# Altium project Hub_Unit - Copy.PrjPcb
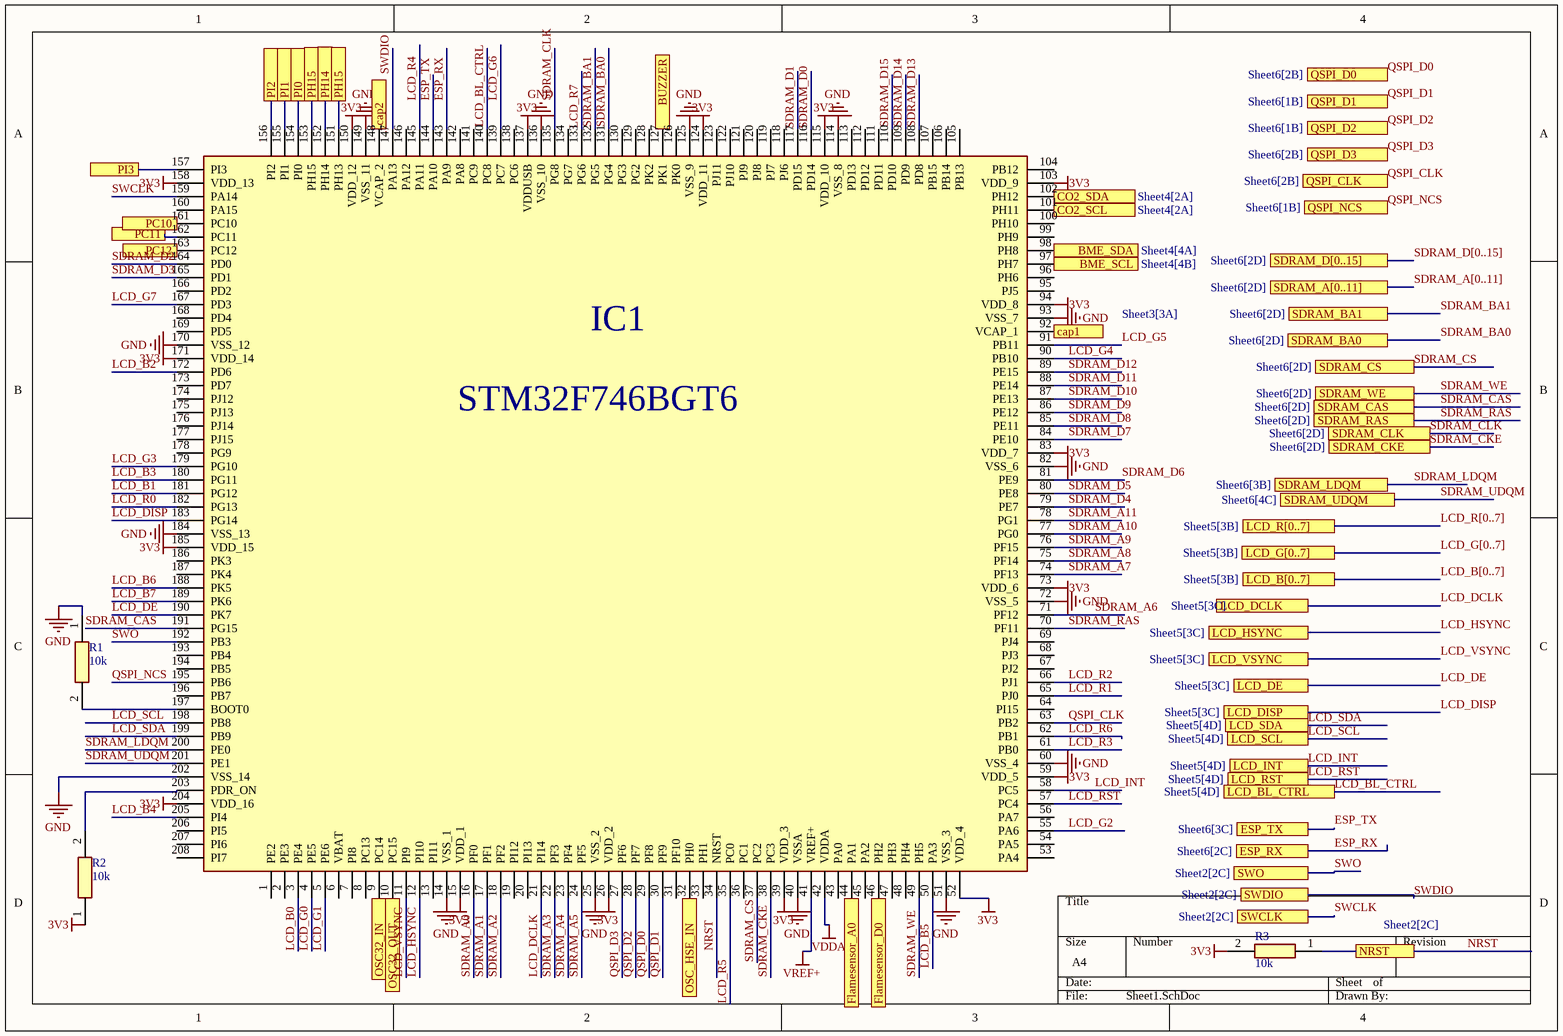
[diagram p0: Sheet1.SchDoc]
6 sheets, 122 parts. Net scope: flat (ports and power ports of the same name join across sheets).
Board file: PCB1.PcbDoc
Sheets:
  Sheet1.SchDoc
  Sheet2.SchDoc
  Sheet3.SchDoc
  Sheet4.SchDoc
  Sheet5.SchDoc
  Sheet6.SchDoc

## Sheet Sheet1.SchDoc
size A4; SheetNumber: 1; SheetTotal: 6

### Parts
IC1  STM32F746BGT6  [QFP50P3000X3000X160-208N]
R1  10k  [RESC1608X55N]
R2  10k  [RESC1608X55N]
R3  10k  [RESC1608X55N]

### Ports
BME_SCL (see Sheet4[4B]), BME_SDA (see Sheet4[4A]), BUZZER, cap1 (see Sheet3[3A]), cap2, CO2_SCL (see Sheet4[2A]), CO2_SDA (see Sheet4[2A]), ESP_RX (see Sheet6[2C]), ESP_TX (see Sheet6[3C]), Flamesensor_A0, Flamesensor_D0, LCD_B[0..7] (see Sheet5[3B]), LCD_BL_CTRL (see Sheet5[4D]), LCD_DCLK (see Sheet5[3C]), LCD_DE (see Sheet5[3C]), LCD_DISP (see Sheet5[3C]), LCD_G[0..7] (see Sheet5[3B]), LCD_HSYNC (see Sheet5[3C]), LCD_INT (see Sheet5[4D]), LCD_R[0..7] (see Sheet5[3B]), LCD_RST (see Sheet5[4D]), LCD_SCL (see Sheet5[4D]), LCD_SDA (see Sheet5[4D]), LCD_VSYNC (see Sheet5[3C]), NRST (see Sheet2[2C]), OSC32_IN, OSC32_OUT, OSC_HSE_IN, PC10, PC11, PC12, PH14, PH15, PI0, PI1, PI2, PI3, QSPI_CLK (see Sheet6[2B]), QSPI_D0 (see Sheet6[2B]), QSPI_D1 (see Sheet6[1B]), QSPI_D2 (see Sheet6[1B]), QSPI_D3 (see Sheet6[2B]), QSPI_NCS (see Sheet6[1B]), SDRAM_A[0..11] (see Sheet6[2D]), SDRAM_BA0 (see Sheet6[2D]), SDRAM_BA1 (see Sheet6[2D]), SDRAM_CAS (see Sheet6[2D]), SDRAM_CKE (see Sheet6[2D]), SDRAM_CLK (see Sheet6[2D]), SDRAM_CS (see Sheet6[2D]), SDRAM_D[0..15] (see Sheet6[2D]), SDRAM_LDQM (see Sheet6[3B]), SDRAM_RAS (see Sheet6[2D]), SDRAM_UDQM (see Sheet6[4C]), SDRAM_WE (see Sheet6[2D]), SWCLK (see Sheet2[2C]), SWDIO (see Sheet2[2C]), SWO (see Sheet2[2C])

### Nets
3V3: IC1.15(VDD_1) IC1.26(VDD_2) IC1.39(VDD_3) IC1.52(VDD_4) IC1.59(VDD_5) IC1.73(VDD_6) IC1.83(VDD_7) IC1.94(VDD_8) IC1.103(VDD_9) IC1.115(VDD_10) IC1.124(VDD_11) IC1.137(VDDUSB) IC1.150(VDD_12) IC1.158(VDD_13) IC1.171(VDD_14) IC1.185(VDD_15) IC1.204(VDD_16) R2.1 R3.2
GND: IC1.14(VSS_1) IC1.25(VSS_2) IC1.40(VSSA) IC1.51(VSS_3) IC1.60(VSS_4) IC1.72(VSS_5) IC1.82(VSS_6) IC1.93(VSS_7) IC1.114(VSS_8) IC1.125(VSS_9) IC1.136(VSS_10) IC1.149(VSS_11) IC1.170(VSS_12) IC1.184(VSS_13) IC1.202(VSS_14) R1.1
VDDA: IC1.42(VDDA)
VREF+: IC1.41(VREF+)
ESP_RX: IC1.143(PA9) ; port ESP_RX
ESP_TX: IC1.144(PA10) ; port ESP_TX
LCD_B0: IC1.3(PE4)
LCD_B1: IC1.181(PG12)
LCD_B2: IC1.172(PD6)
LCD_B3: IC1.180(PG11)
LCD_B4: IC1.205(PI4)
LCD_B5: IC1.50(PA3)
LCD_B6: IC1.188(PK5)
LCD_B7: IC1.189(PK6)
LCD_BL_CTRL: IC1.140(PC8) ; port LCD_BL_CTRL
LCD_DCLK: IC1.21(PI14) ; port LCD_DCLK
LCD_DE: IC1.190(PK7) ; port LCD_DE
LCD_DISP: IC1.183(PG14) ; port LCD_DISP
LCD_G0: IC1.4(PE5)
LCD_G1: IC1.5(PE6)
LCD_G2: IC1.55(PA6)
LCD_G3: IC1.179(PG10)
LCD_G4: IC1.90(PB10)
LCD_G5: IC1.91(PB11)
LCD_G6: IC1.139(PC7)
LCD_G7: IC1.167(PD3)
LCD_HSYNC: IC1.12(PI10) ; port LCD_HSYNC
LCD_INT: IC1.58(PC5) ; port LCD_INT
LCD_R0: IC1.182(PG13)
LCD_R1: IC1.65(PJ0)
LCD_R2: IC1.66(PJ1)
LCD_R3: IC1.61(PB0)
LCD_R4: IC1.145(PA11)
LCD_R5: IC1.35(PC0)
LCD_R6: IC1.62(PB1)
LCD_R7: IC1.133(PG6)
LCD_RST: IC1.57(PC4) ; port LCD_RST
LCD_SCL: IC1.198(PB8) ; port LCD_SCL
LCD_SDA: IC1.199(PB9) ; port LCD_SDA
LCD_VSYNC: IC1.11(PI9) ; port LCD_VSYNC
NRST: IC1.34(NRST) R3.1 ; port NRST
QSPI_CLK: IC1.63(PB2) ; port QSPI_CLK
QSPI_D0: IC1.29(PF8) ; port QSPI_D0
QSPI_D1: IC1.30(PF9) ; port QSPI_D1
QSPI_D2: IC1.28(PF7) ; port QSPI_D2
QSPI_D3: IC1.27(PF6) ; port QSPI_D3
QSPI_NCS: IC1.195(PB6) ; port QSPI_NCS
SDRAM_A0: IC1.16(PF0)
SDRAM_A1: IC1.17(PF1)
SDRAM_A2: IC1.18(PF2)
SDRAM_A3: IC1.22(PF3)
SDRAM_A4: IC1.23(PF4)
SDRAM_A5: IC1.24(PF5)
SDRAM_A6: IC1.71(PF12)
SDRAM_A7: IC1.74(PF13)
SDRAM_A8: IC1.75(PF14)
SDRAM_A9: IC1.76(PF15)
SDRAM_A10: IC1.77(PG0)
SDRAM_A11: IC1.78(PG1)
SDRAM_BA0: IC1.131(PG4) ; port SDRAM_BA0
SDRAM_BA1: IC1.132(PG5) ; port SDRAM_BA1
SDRAM_CAS: IC1.191(PG15) ; port SDRAM_CAS
SDRAM_CKE: IC1.38(PC3) ; port SDRAM_CKE
SDRAM_CLK: IC1.135(PG8) ; port SDRAM_CLK
SDRAM_CS: IC1.37(PC2) ; port SDRAM_CS
SDRAM_D0: IC1.116(PD14)
SDRAM_D1: IC1.117(PD15)
SDRAM_D2: IC1.164(PD0)
SDRAM_D3: IC1.165(PD1)
SDRAM_D4: IC1.79(PE7)
SDRAM_D5: IC1.80(PE8)
SDRAM_D6: IC1.81(PE9)
SDRAM_D7: IC1.84(PE10)
SDRAM_D8: IC1.85(PE11)
SDRAM_D9: IC1.86(PE12)
SDRAM_D10: IC1.87(PE13)
SDRAM_D11: IC1.88(PE14)
SDRAM_D12: IC1.89(PE15)
SDRAM_D13: IC1.108(PD8)
SDRAM_D14: IC1.109(PD9)
SDRAM_D15: IC1.110(PD10)
SDRAM_LDQM: IC1.200(PE0) ; port SDRAM_LDQM
SDRAM_RAS: IC1.70(PF11) ; port SDRAM_RAS
SDRAM_UDQM: IC1.201(PE1) ; port SDRAM_UDQM
SDRAM_WE: IC1.49(PH5) ; port SDRAM_WE
SWCLK: IC1.159(PA14) ; port SWCLK
SWDIO: IC1.147(PA13) ; port SWDIO
SWO: IC1.192(PB3) ; port SWO
NetC6_1: IC1.148(VCAP_2) ; port cap2
NetC7_1: IC1.92(VCAP_1) ; port cap1
NetC22_2: IC1.9(PC14) ; port OSC32_IN
NetC23_2: IC1.10(PC15) ; port OSC32_OUT
NetC41_2: IC1.44(PA1) ; port Flamesensor_A0
NetIC1_32: IC1.32(PH0) ; port OSC_HSE_IN
NetIC1_46: IC1.46(PH2) ; port Flamesensor_D0
NetIC1_97: IC1.97(PH7) ; port BME_SCL
NetIC1_98: IC1.98(PH8) ; port BME_SDA
NetIC1_101: IC1.101(PH11) ; port CO2_SCL
NetIC1_102: IC1.102(PH12) ; port CO2_SDA
NetIC1_127: IC1.127(PK1) ; port BUZZER
NetIC1_151: IC1.151(PH13) IC1.153(PH15) ; port PH15
NetIC1_152: IC1.152(PH14) ; port PH14
NetIC1_154: IC1.154(PI0) ; port PI0
NetIC1_155: IC1.155(PI1) ; port PI1
NetIC1_156: IC1.156(PI2) ; port PI2
NetIC1_157: IC1.157(PI3) ; port PI3
NetIC1_161: IC1.161(PC10) ; port PC10
NetIC1_162: IC1.162(PC11) ; port PC11
NetIC1_163: IC1.163(PC12) ; port PC12
NetIC1_197: IC1.197(BOOT0) R1.2
NetIC1_203: IC1.203(PDR_ON) R2.2

Not connected (* = marked no-connect by the designer): IC1 1(PE2) 2(PE3) 6(VBAT) 7(PI8) 8(PC13) 13(PI11) 19(PI12) 20(PI13) 31(PF10) 33(PH1) 36(PC1) 43(PA0) 45(PA2) 47(PH3) 48(PH4) 53(PA4) 54(PA5) 56(PA7) 64(PI15) 67(PJ2) 68(PJ3) 69(PJ4) 95(PJ5) 96(PH6) 99(PH9) 100(PH10) 104(PB12) 105(PB13) 106(PB14) 107(PB15) 111(PD11) 112(PD12) 113(PD13) 118(PJ6) 119(PJ7) 120(PJ8) 121(PJ9) 122(PJ10) 123(PJ11) 126(PK0) 128(PK2) 129(PG2) 130(PG3) 134(PG7) 138(PC6) 141(PC9) 142(PA8) 146(PA12) 160(PA15) 166(PD2) 168(PD4) 169(PD5) 173(PD7) 174(PJ12) 175(PJ13) 176(PJ14) 177(PJ15) 178(PG9) 186(PK3) 187(PK4) 193(PB4) 194(PB5) 196(PB7) 206(PI5) 207(PI6) 208(PI7)

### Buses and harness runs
bus LCD_B[0..7] = port LCD_B[0..7]
bus LCD_G[0..7] = port LCD_G[0..7]
bus LCD_R[0..7] = port LCD_R[0..7]
bus SDRAM_A[0..11] = port SDRAM_A[0..11]
bus SDRAM_D[0..15] = port SDRAM_D[0..15]

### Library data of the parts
IC1 = STM32F746BGT6: Integrated Circuit; Manufacturer_Name: STMicroelectronics
R1-R3 = RC0603FR-071KL: Resistor; Manufacturer_Name: YAGEO

## Sheet Sheet2.SchDoc
size A4; SheetNumber: 2; SheetTotal: 6
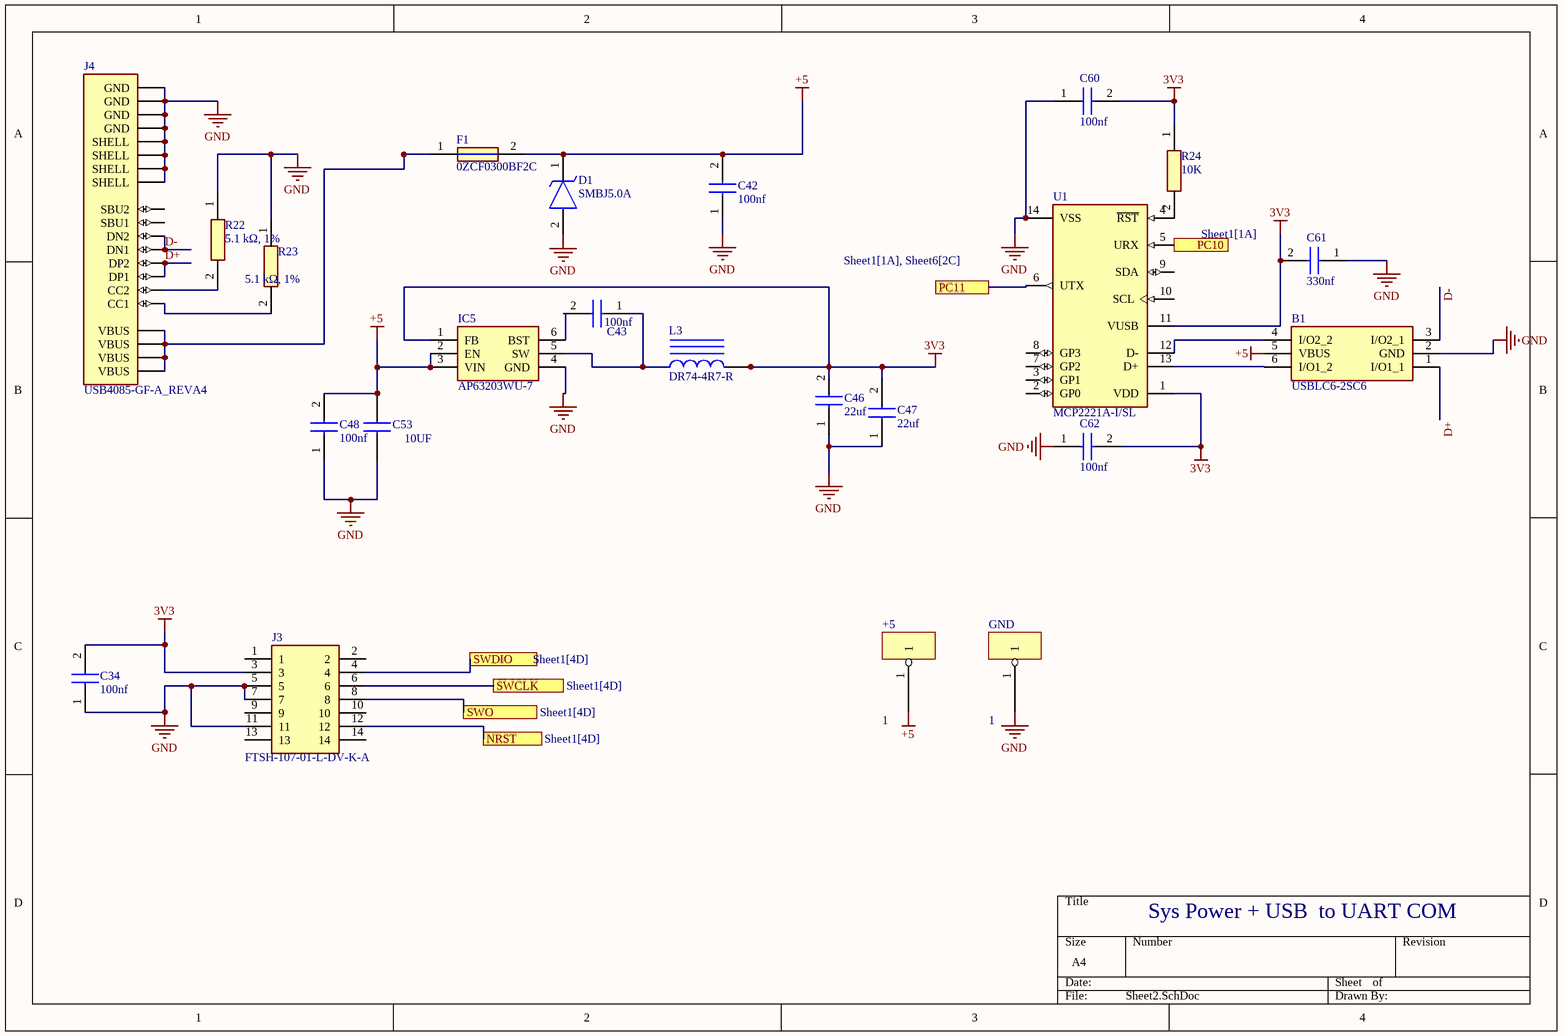
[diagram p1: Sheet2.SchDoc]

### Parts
+5  1  [ANT]
B1  USBLC6-2SC6  [SOT95P280X145-6N]
C34  100nf  [CAPC1608X95N]
C42  100nf  [CAPC1608X95N]
C43  100nf  [CAPC1608X95N]
C46  22uf  [CAPC1608X95N]
C47  22uf  [CAPC1608X95N]
C48  100nf  [CAPC1608X95N]
C53  10UF  [CAPC1608X90N]
C60  100nf  [CAPC1608X95N]
C61  330nf  [CAPC1608X95N]
C62  100nf  [CAPC1608X95N]
D1  SMBJ5.0A  [SMBJ12A]
F1  0ZCF0300BF2C  [FUSC7451X115N]
GND  1  [ANT]
IC5  AP63203WU-7  [AP63203WU7]
J3  FTSH-107-01-L-DV-K-A  [FTSH-107-XX-YYY-DV-K-A]
J4  USB4085-GF-A_REVA4  [GCT_USB4085-GF-A_REVA4]
L3  DR74-4R7-R  [COBU-DR74-4R7-R_V]
R22  5.1 kΩ, 1%  [RESC1608X55N]
R23  5.1 kΩ, 1%  [RESC1608X55N]
R24  10K  [RESC1608X55N]
U1  MCP2221A-I/SL  [FP-C04-065-SL-MFG]

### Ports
NRST (see Sheet1[4D]), PC10 (see Sheet1[1A]), PC11 (see Sheet1[1A], Sheet6[2C]), SWCLK (see Sheet1[4D]), SWDIO (see Sheet1[4D]), SWO (see Sheet1[4D])

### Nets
3V3: C34.2 C46.2 C47.2 C60.2 C61.2 C62.2 IC5.1(FB) J3.3 L3.2 R24.1 U1.1(VDD) U1.11(VUSB)
+5: +5.1 B1.5(VBUS) C42.2 C48.2 C53.2 D1.1(K) F1.2 IC5.2(EN) IC5.3(VIN)
GND: B1.2(GND) C34.1 C42.1 C46.1 C47.1 C48.1 C53.1 C60.1 C61.1 C62.1 D1.2(A) GND.1 IC5.4(GND) J3.5 J3.7 J3.11 J4.A1(GND) J4.A12(GND) J4.B1(GND) J4.B12(GND) J4.S1(SHELL) J4.S2(SHELL) J4.S3(SHELL) J4.S4(SHELL) R22.1 R23.1 U1.14(VSS)
D+: B1.1(I/O1_1) J4.A6(DP1) J4.B6(DP2)
D-: B1.3(I/O2_1) J4.A7(DN1) J4.B7(DN2)
NRST: J3.12 ; port NRST
SWCLK: J3.6 ; port SWCLK
SWDIO: J3.4 ; port SWDIO
SWO: J3.8 ; port SWO
NetB1_4: B1.4(I/O2_2) U1.12(D-)
NetB1_6: B1.6(I/O1_2) U1.13(D+)
NetC43_1: C43.1 IC5.5(SW) L3.1
NetC43_2: C43.2 IC5.6(BST)
NetF1_1: F1.1 J4.A4(VBUS) J4.A9(VBUS) J4.B4(VBUS) J4.B9(VBUS)
NetIC1_161: U1.5(URX) ; port PC10
NetIC1_162: U1.6(UTX) ; port PC11
NetJ4_A5: J4.A5(CC1) R23.2
NetJ4_B5: J4.B5(CC2) R22.2
NetR24_2: R24.2 U1.4(~{RST})

Not connected (* = marked no-connect by the designer): J3 1 2 9 10 13 14; J4 A8(SBU1) B8(SBU2); U1 2(GP0) 3(GP1) 7(GP2) 8(GP3) 9(SDA) 10(SCL)

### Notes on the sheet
- Sys Power + USB  to UART COM

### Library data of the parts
B1 = USBLC6-2SC6: TVS Diode Array Uni-Directional USBLC6-2SC6 17V, SOT-23 6-Pin; Manufacturer_Name: STMicroelectronics; Geometry.Height: 1.45mm
C34 C42 C43 C46-C48 C60-C62 = VJ0603Y104KXACW1BC: Capacitor; Manufacturer_Name: Vishay
C53 = CL10A106KP8NNNC: 10F +/-10% 10V Ceramic Capacitor X5R 0603 (1608 Metric); Manufacturer_Name: SAMSUNG; Geometry.Height: 0.9mm
D1 = SMBJ5.0A: TVS Diode (Uni-directional); Manufacturer_Name: STMicroelectronics
F1 = 0ZCF0300BF2C: Fuse; Manufacturer_Name: BelFuse
IC5 = AP63203WU-7: Integrated Circuit; Manufacturer_Name: Diodes Incorporated
J3 = FTSH-107-01-L-DV-K-A: Connector; Manufacturer_Name: SAMTEC
J4 = USB4085-GF-A_REVA4: USB-C (USB TYPE-C) USB 2.0 Receptacle Connector 24 (16+8 Dummy) Position Through Hole, Right Angle, low cost, 3.46mm profile, 16 pin, horizontal, Top mount; MF: Global Connector Technology
L3 = CMP-2000-06180-1: High Power Density, High Efficiency, Shielded Inductor, 4.7 uH, -40 to 125 degC, RoHS, Tape and Reel; Manufacturer: Eaton; Tolerance: ±20%; Current - Saturation: 4.37A; Type: Wirewound; Frequency - Test: 100kHz; Current Rating: 3.34A; DC Resistance (DCR): 25.4mOhm; Inductance: 4.7µH; Material - Core: Ferrite
R22-R24 = RC0603FR-071KL: Resistor; Manufacturer_Name: YAGEO
U1 = CMP-06284-000011-1: IC USB TO I2C/UART 14SOIC; Manufacturer: Microchip; Min Supply Voltage: 3V; Usb Standard: USB 2.0; Max Supply Voltage: 5.5V; Nominal Supply Current: 10-13mA; Automotive Grade: Grade 3; Interface: I2C,UART,USB; Standoff Height: 0.1mm; Max Junction Temp: +150°C; Data Rate: 12Mbits/s

## Sheet Sheet3.SchDoc
size A4; SheetNumber: 3; SheetTotal: 6
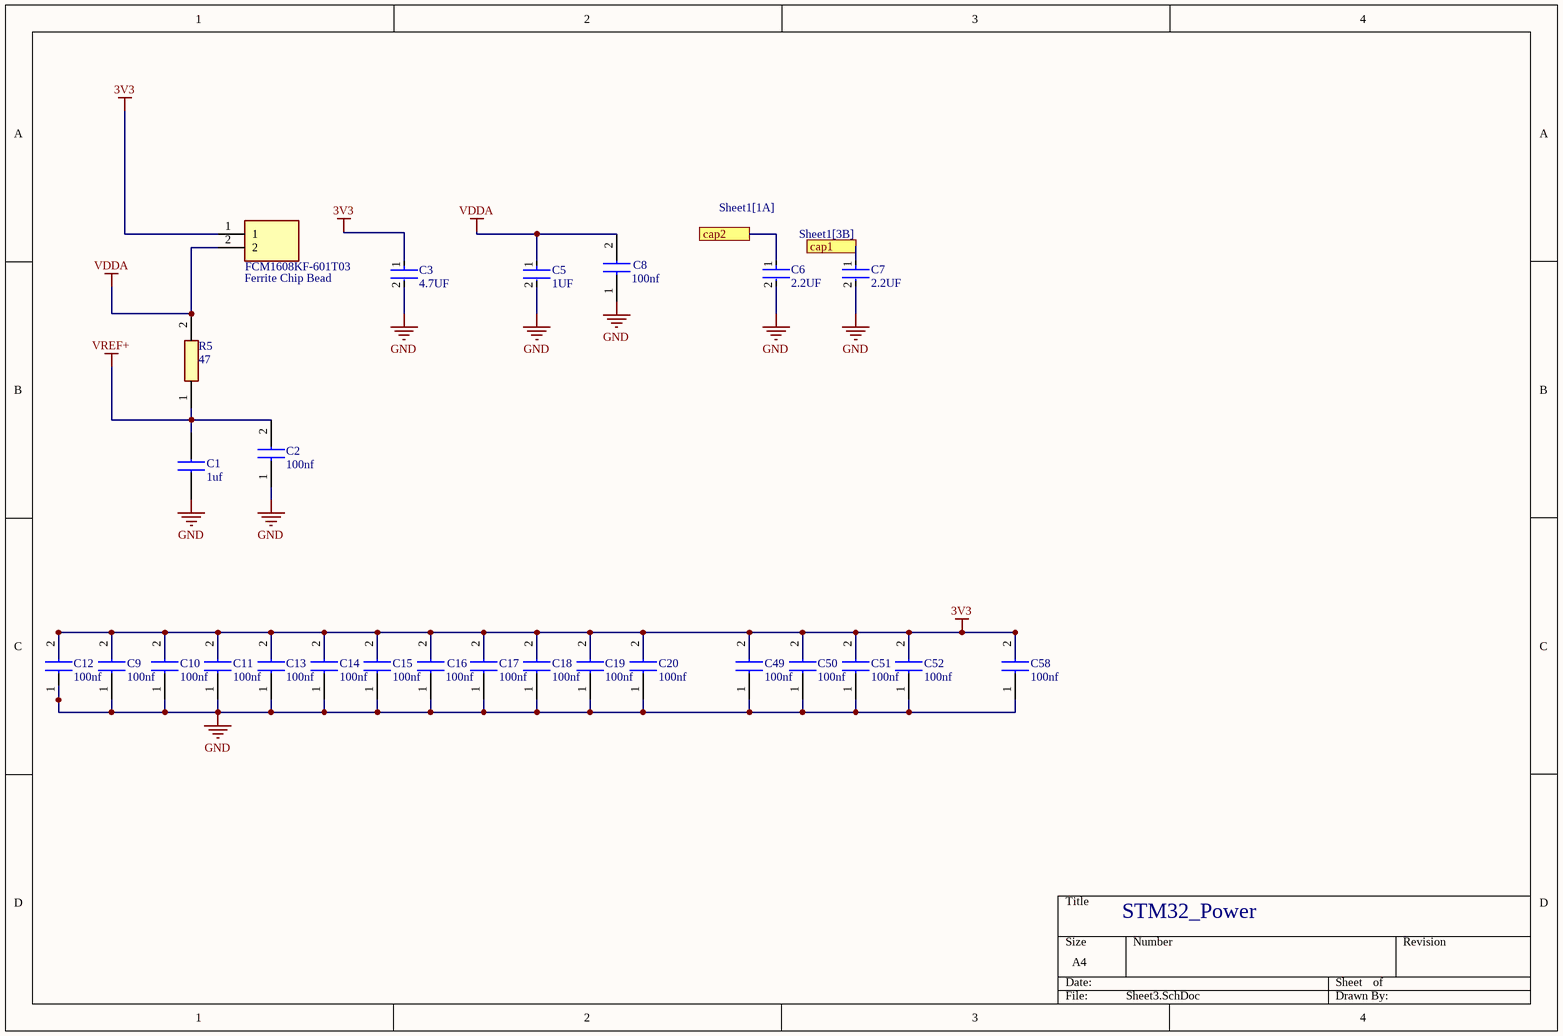
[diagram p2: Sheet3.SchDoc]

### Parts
C1  1uf  [CAPC1608X95N]
C2  100nf  [CAPC1608X95N]
C3  4.7UF  [FP-CL10-IPC_A]
C5  1UF  [FP-CL10-IPC_A]
C6  2.2UF  [FP-CL10-IPC_A]
C7  2.2UF  [FP-CL10-IPC_A]
C8  100nf  [CAPC1608X95N]
C9  100nf  [CAPC1608X95N]
C10  100nf  [CAPC1608X95N]
C11  100nf  [CAPC1608X95N]
C12  100nf  [CAPC1608X95N]
C13  100nf  [CAPC1608X95N]
C14  100nf  [CAPC1608X95N]
C15  100nf  [CAPC1608X95N]
C16  100nf  [CAPC1608X95N]
C17  100nf  [CAPC1608X95N]
C18  100nf  [CAPC1608X95N]
C19  100nf  [CAPC1608X95N]
C20  100nf  [CAPC1608X95N]
C49  100nf  [CAPC1608X95N]
C50  100nf  [CAPC1608X95N]
C51  100nf  [CAPC1608X95N]
C52  100nf  [CAPC1608X95N]
C58  100nf  [CAPC1608X95N]
Ferrite_Chip_Bead  FCM1608KF-601T03  [BEADC1608X95N]
R5  47  [RESC1608X55N]

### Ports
cap1 (see Sheet1[3B]), cap2 (see Sheet1[1A])

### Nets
3V3: C3.1 C9.2 C10.2 C11.2 C12.2 C13.2 C14.2 C15.2 C16.2 C17.2 C18.2 C19.2 C20.2 C49.2 C50.2 C51.2 C52.2 C58.2 Ferrite_Chip_Bead.1
GND: C1.1 C2.1 C3.2 C5.2 C6.2 C7.2 C8.1 C9.1 C10.1 C11.1 C12.1 C13.1 C14.1 C15.1 C16.1 C17.1 C18.1 C19.1 C20.1 C49.1 C50.1 C51.1 C52.1 C58.1
VDDA: C5.1 C8.2 Ferrite_Chip_Bead.2 R5.2
VREF+: C1.2 C2.2 R5.1
NetC6_1: C6.1 ; port cap2
NetC7_1: C7.1 ; port cap1

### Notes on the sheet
- STM32_Power

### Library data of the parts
C1 = 0603X105K250CT: WALSIN - 0603X105K250CT - SMD Multilayer Ceramic Capacitor, 1 F, 25 V, 0603 [1608 Metric], +/- 10%, X5R; Manufacturer_Name: Walsin Technology Corporation; Geometry.Height: 0.95mm
C2 C8-C20 C49-C52 C58 = VJ0603Y104KXACW1BC: Capacitor; Manufacturer_Name: Vishay
C3 C5-C7 = CMP-13271-003582-1: Cap Ceramic 2.2uF 10V X7R ±10% Pad SMD 0603 +125°C T/R
Ferrite_Chip_Bead = FCM1608KF-601T03: Ferrite Bead; Manufacturer_Name: TAI-TECH
R5 = RC0603FR-071KL: Resistor; Manufacturer_Name: YAGEO

## Sheet Sheet4.SchDoc
size A4; SheetNumber: 4; SheetTotal: 6
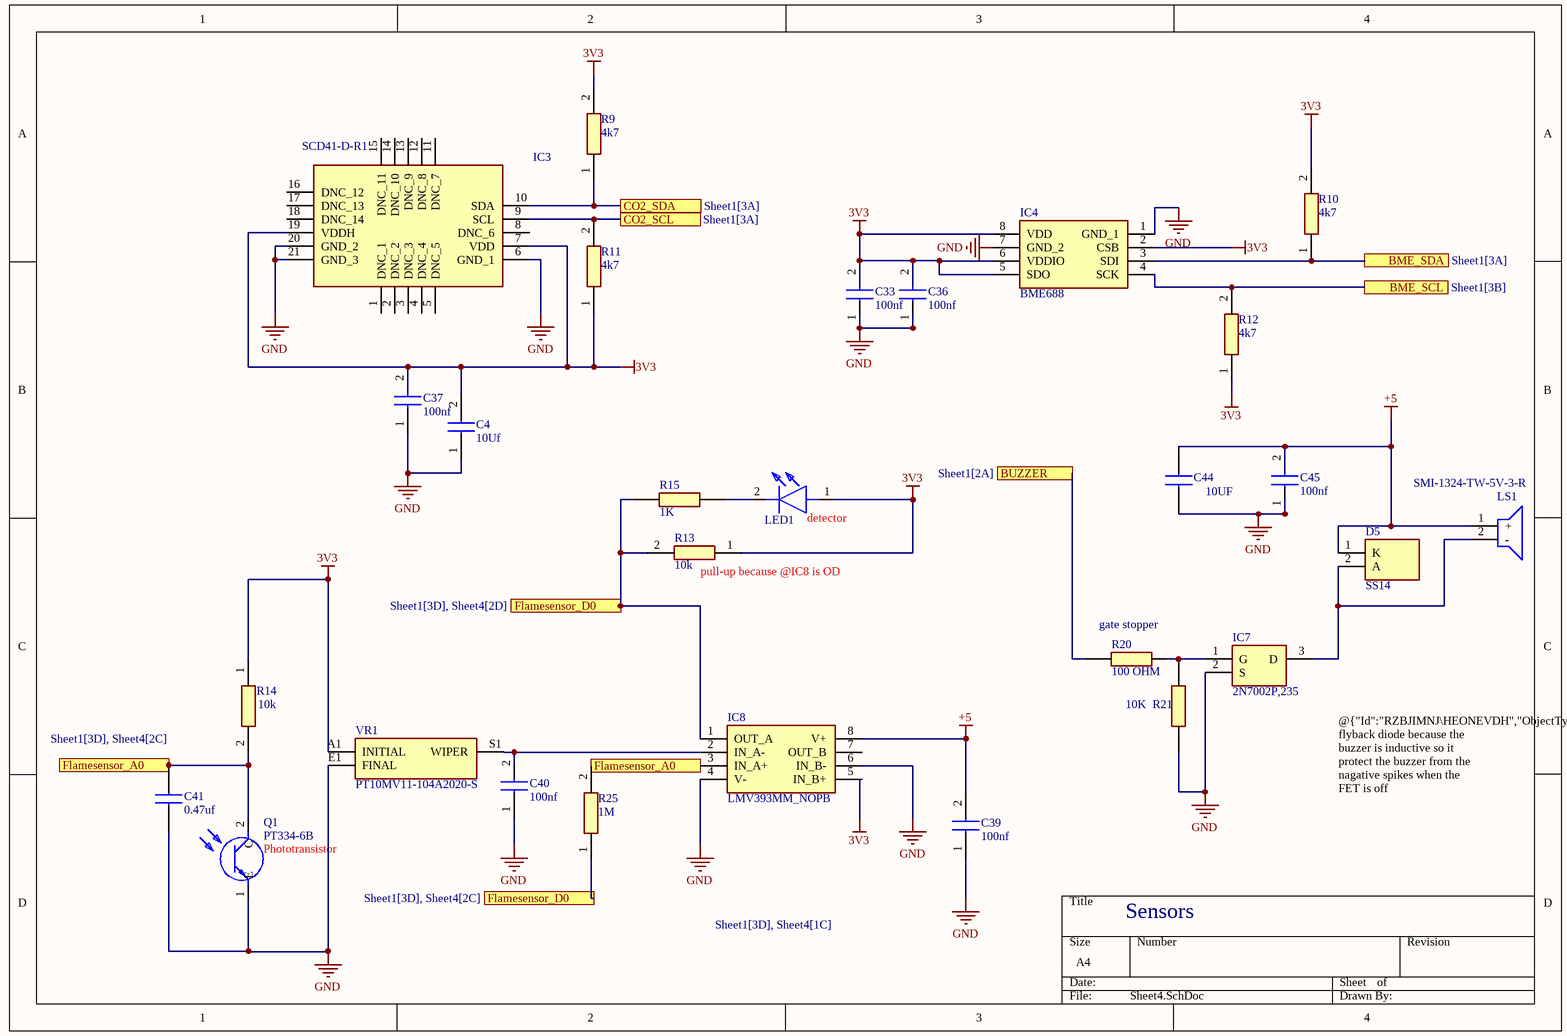
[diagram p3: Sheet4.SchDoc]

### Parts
C4  10Uf  [CAPC1608X95N]
C33  100nf  [CAPC1608X95N]
C36  100nf  [CAPC1608X95N]
C37  100nf  [CAPC1608X95N]
C39  100nf  [CAPC1608X95N]
C40  100nf  [CAPC1608X95N]
C41  0.47uf  [CAPC1608X90N]
C44  10UF  [CAPC1608X90N]
C45  100nf  [CAPC1608X95N]
D5  SS14  [DIOM5026X262N]
IC3  SCD41-D-R1  [SCD41DR1]
IC4  BME688  [BME688]
IC7  2N7002P,235  [SOT95P230X110-3N]
IC8  LMV393MM_NOPB  [SOP65P490X110-8N]
LED1  KPTL-3216SURCK-01-VS  [KPTL3216SURCK01VS]  (value not drawn)
LS1  SMI-1324-TW-5V-3-R  [SMI1324TW5V3R]
Q1  PT334-6B  [PT3346B]
R9  4k7  [RESC1608X55N]
R10  4k7  [RESC1608X55N]
R11  4k7  [RESC1608X55N]
R12  4k7  [RESC1608X55N]
R13  10k  [RESC1608X55N]
R14  10k  [RESC1608X55N]
R15  1K  [RESC1608X50N]
R20  100 OHM  [RESC1608X55N]
R21  10K  [RESC1608X50N]
R25  1M  [RESC1608X55N]
VR1  PT10MV11-104A2020-S  [PT10MV11104A2020S]

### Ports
BME_SCL (see Sheet1[3B]), BME_SDA (see Sheet1[3A]), BUZZER (see Sheet1[2A]), CO2_SCL (see Sheet1[3A]), CO2_SDA (see Sheet1[3A]), Flamesensor_A0 (see Sheet1[3D], Sheet4[1C]), Flamesensor_A0 (see Sheet1[3D], Sheet4[2C]), Flamesensor_D0 (see Sheet1[3D], Sheet4[2C]), Flamesensor_D0 (see Sheet1[3D], Sheet4[2D])

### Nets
3V3: C4.2 C33.2 C36.2 C37.2 IC3.7(VDD) IC3.19(VDDH) IC4.2(CSB) IC4.5(SDO) IC4.6(VDDIO) IC4.8(VDD) IC8.5(IN_B+) LED1.1(A) R9.2 R10.2 R11.1 R12.1 R13.1 R14.1 VR1.A1(INITIAL)
+5: C39.2 C44.2 C45.2 D5.1(K) IC8.8(V+) LS1.1(+)
GND: C4.1 C33.1 C36.1 C37.1 C39.1 C40.1 C41.1 C44.1 C45.1 IC3.6(GND_1) IC3.20(GND_2) IC3.21(GND_3) IC4.1(GND_1) IC4.7(GND_2) IC7.2(S) IC8.4(V-) IC8.6(IN_B-) Q1.1(E) R21.1 VR1.E1(FINAL)
NetC40_2: C40.2 IC8.2(IN_A-) VR1.S1(WIPER)
NetC41_2: C41.2 IC8.3(IN_A+) Q1.2(C) R14.2 R25.2 ; port Flamesensor_A0
NetD5_2: D5.2(A) IC7.3(D) LS1.2(-)
NetIC1_46: IC8.1(OUT_A) R13.2 R15.1 R25.1 ; port Flamesensor_D0
NetIC1_97: IC4.4(SCK) R12.2 ; port BME_SCL
NetIC1_98: IC4.3(SDI) R10.1 ; port BME_SDA
NetIC1_101: IC3.9(SCL) R11.2 ; port CO2_SCL
NetIC1_102: IC3.10(SDA) R9.1 ; port CO2_SDA
NetIC1_127: R20.1 ; port BUZZER
NetIC7_1: IC7.1(G) R20.2 R21.2
NetLED1_2: LED1.2(K) R15.2

Not connected (* = marked no-connect by the designer): IC3 1(DNC_1) 2(DNC_2) 3(DNC_3) 4(DNC_4) 5(DNC_5) 8(DNC_6) 11(DNC_7) 12(DNC_8) 13(DNC_9) 14(DNC_10) 15(DNC_11) 16(DNC_12) 17(DNC_13) 18(DNC_14); IC8 7(OUT_B)

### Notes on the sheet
- (near R13) pull-up because @IC8 is OD
- (near LED1) detector
- (near R20) gate stopper
- @{"Id":"RZBJIMNJ\HEONEVDH","ObjectType":2}
  flyback diode because the buzzer is inductive so it protect the buzzer from the nagative spikes when the FET is off
- (near Q1) Phototransistor
- Sensors

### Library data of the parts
C4 C33 C36 C37 C39 C40 C45 = VJ0603Y104KXACW1BC: Capacitor; Manufacturer_Name: Vishay
C41 = CC0603KRX7R6BB474: Phycomp 0603 Standard 470nF Ceramic Multilayer Capacitor, 10 V dc, +125C, X7R Dielectric, +/-10% SMD; Manufacturer_Name: KEMET; Geometry.Height: 0.9mm
C44 = CL10A106KP8NNNC: as C53 on sheet Sheet2
D5 = SS14: Battery; Manufacturer_Name: HY Electronic
IC3 = SCD41-D-R1: Integrated Circuit; Manufacturer_Name: Sensirion
IC4 = BME688: Integrated Circuit; Manufacturer_Name: BOSCH
IC7 = 2N7002P,235: Integrated Circuit; Manufacturer_Name: Nylofix
IC8 = LMV393MM_NOPB: Integrated Circuit; Manufacturer_Name: Texas Instruments; Manufacturer_Part_Number: LMV393MM/NOPB
LED1 = KPTL-3216SURCK-01-VS: LED; Manufacturer_Name: Kingbright
LS1 = SMI-1324-TW-5V-3-R: Loudspeaker or Buzzer; Manufacturer_Name: PUI Audio
Q1 = PT334-6B: Phototransistor; Manufacturer_Name: Everlight
R9-R12 = CRCW06034K70JNEAC: Resistor; Manufacturer_Name: Vishay
R13 R14 R25 = RC0603FR-071KL: Resistor; Manufacturer_Name: YAGEO
R15 = CRCW06031K00FKEA: CRCW0603 Resistor T/R 0.10W,1%,1K Vishay CRCW Series Thick Film Surface Mount Resistor 0603 Case 1k +/-1% 0.1W +/-100ppm/C; Geometry.Height: 0.5mm
R20 = TNPW0603100RFHEA: Res Thin Film 0603 100 Ohm 1% 0.1W(1/10W) +/-50ppm/C Sulfur Resistant Pad SMD Automotive Medical T/R; Manufacturer_Name: Vishay; Geometry.Height: 0.55mm
R21 = RCA0603100KFKEA: 100 kOhms +/-1% 0.1W, 1/10W Chip Resistor 0603 (1608 Metric) Anti-Sulfur, Automotive AEC-Q200 Thick Film; Manufacturer_Name: Vishay; Geometry.Height: 0.5mm
VR1 = PT10MV11-104A2020-S: Variable Resistor; Manufacturer_Name: PIHER

## Sheet Sheet5.SchDoc
size A4; SheetNumber: 5; SheetTotal: 6
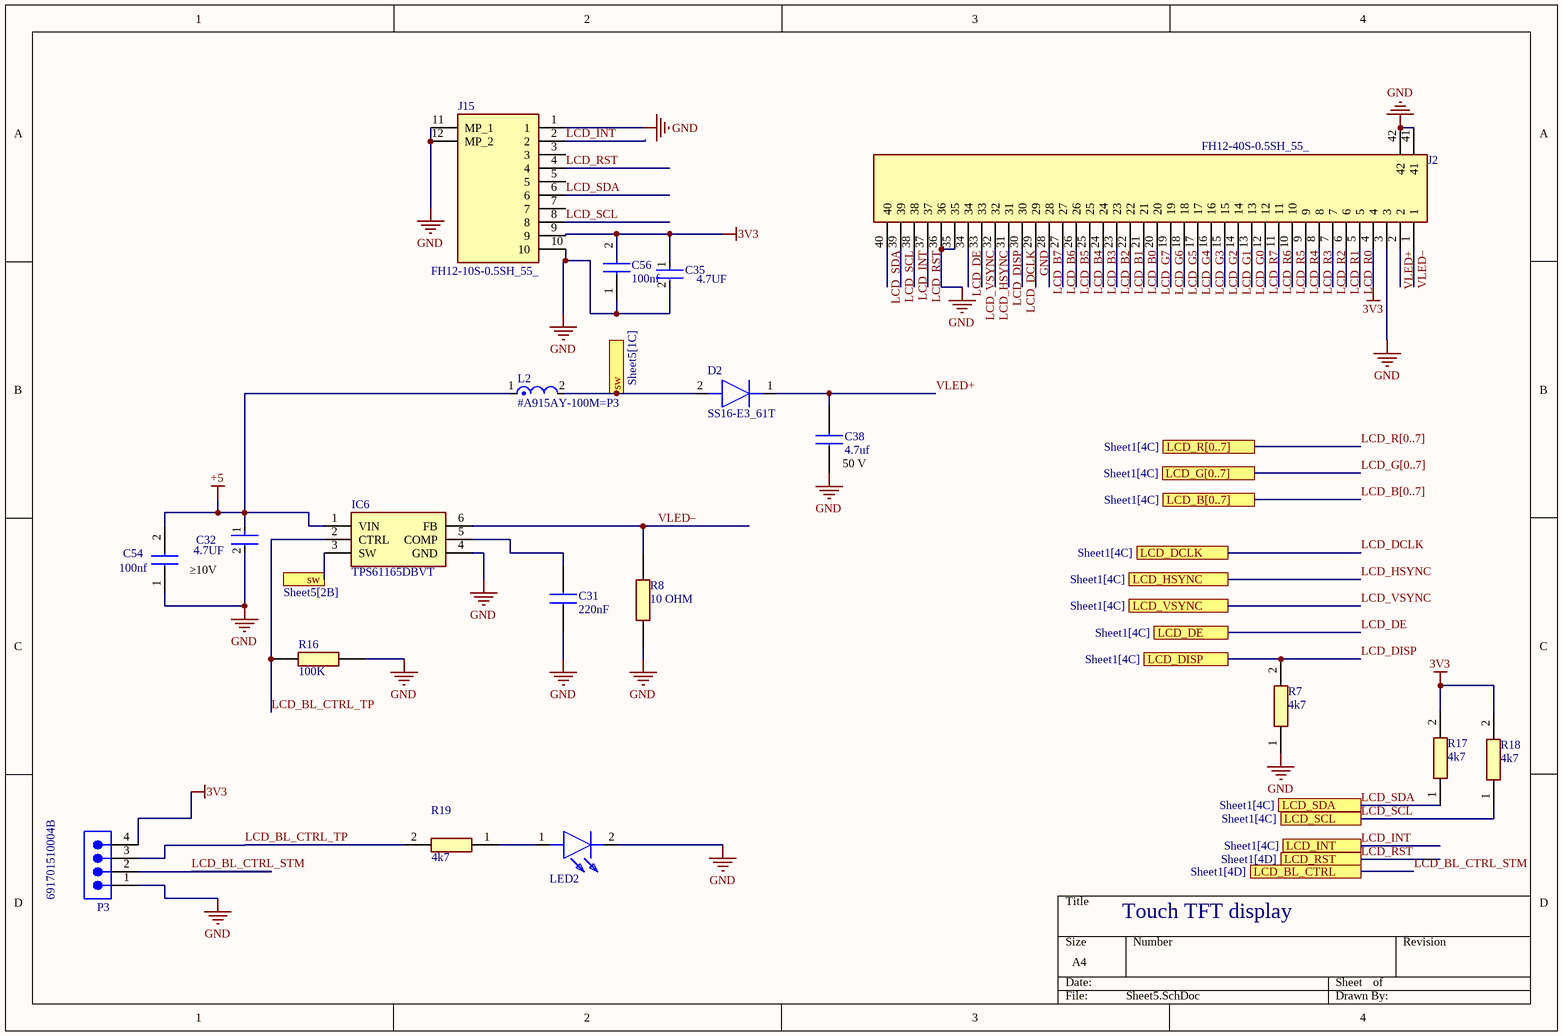
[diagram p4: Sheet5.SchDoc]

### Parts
C31  220nF  [CAPC1608X87N]
C32  4.7UF  [FP-CL10-IPC_A]
C35  4.7UF  [FP-CL10-IPC_A]
C38  4.7uf  [CAPC1608X95N]
C54  100nf  [CAPC1608X95N]
C56  100nf  [CAPC1608X95N]
D2  SS16-E3_61T  [DIOM5127X229N]
IC6  TPS61165DBVT  [SOT95P280X145-6N]
J2  FH12-40S-0.5SH_55_  [FH1240S05SH55]
J15  FH12-10S-0.5SH_55_  [FH1210S05SH55]
L2  #A915AY-100M=P3  [FP-D53LC-MFG]
LED2  KPTL-3216SURCK-01-VS  [KPTL3216SURCK01VS]  (value not drawn)
P3  691701510004B  [691701510004B]
R7  4k7  [RESC1608X55N]
R8  10 OHM  [RESC1608X50N]
R16  100K  [RESC1608X50N]
R17  4k7  [RESC1608X55N]
R18  4k7  [RESC1608X55N]
R19  4k7  [RESC1608X55N]

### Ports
LCD_B[0..7] (see Sheet1[4C]), LCD_BL_CTRL (see Sheet1[4D]), LCD_DCLK (see Sheet1[4C]), LCD_DE (see Sheet1[4C]), LCD_DISP (see Sheet1[4C]), LCD_G[0..7] (see Sheet1[4C]), LCD_HSYNC (see Sheet1[4C]), LCD_INT (see Sheet1[4C]), LCD_R[0..7] (see Sheet1[4C]), LCD_RST (see Sheet1[4D]), LCD_SCL (see Sheet1[4C]), LCD_SDA (see Sheet1[4C]), LCD_VSYNC (see Sheet1[4C]), sw (see Sheet5[1C]), sw (see Sheet5[2B])

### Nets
3V3: C35.1 C56.2 J2.4 J15.9 P3.4 R17.2 R18.2
+5: C32.1 C54.2 IC6.1(VIN) L2.1
GND: C31.1 C32.2 C35.2 C38.1 C54.1 C56.1 IC6.4(GND) J2.3 J2.29 J2.35 J2.36 J2.41 J2.42 J15.1 J15.10 J15.11(MP_1) J15.12(MP_2) LED2.2(K) P3.1 R7.1 R8.1 R16.2
LCD_B0: J2.21
LCD_B1: J2.22
LCD_B2: J2.23
LCD_B3: J2.24
LCD_B4: J2.25
LCD_B5: J2.26
LCD_B6: J2.27
LCD_B7: J2.28
LCD_BL_CTRL_STM: P3.2 ; port LCD_BL_CTRL  [project net LCD_BL_CTRL]
LCD_BL_CTRL_TP: IC6.2(CTRL) P3.3 R16.1 R19.2
LCD_DCLK: J2.30 ; port LCD_DCLK
LCD_DE: J2.34 ; port LCD_DE
LCD_DISP: J2.31 R7.2 ; port LCD_DISP
LCD_G0: J2.13
LCD_G1: J2.14
LCD_G2: J2.15
LCD_G3: J2.16
LCD_G4: J2.17
LCD_G5: J2.18
LCD_G6: J2.19
LCD_G7: J2.20
LCD_HSYNC: J2.32 ; port LCD_HSYNC
LCD_INT: J2.38 J15.2 ; port LCD_INT
LCD_R0: J2.5
LCD_R1: J2.6
LCD_R2: J2.7
LCD_R3: J2.8
LCD_R4: J2.9
LCD_R5: J2.10
LCD_R6: J2.11
LCD_R7: J2.12
LCD_RST: J2.37 J15.4 ; port LCD_RST
LCD_SCL: J2.39 J15.8 R18.1 ; port LCD_SCL
LCD_SDA: J2.40 J15.6 R17.1 ; port LCD_SDA
LCD_VSYNC: J2.33 ; port LCD_VSYNC
VLED+: C38.2 D2.1(K) J2.2
VLED–: IC6.6(FB) J2.1 R8.2
NetC31_2: C31.2 IC6.5(COMP)
NetD2_2: D2.2(A) IC6.3(SW) L2.2 ; port sw
NetLED2_1: LED2.1(A) R19.1

Not connected (* = marked no-connect by the designer): J15 3 5 7

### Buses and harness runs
bus LCD_B[0..7] = port LCD_B[0..7]
bus LCD_G[0..7] = port LCD_G[0..7]
bus LCD_R[0..7] = port LCD_R[0..7]

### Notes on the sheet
- (near C38) 50 V
- ≥10V
- Touch TFT display

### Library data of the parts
C31 = 0603B223K500CT: WALSIN - 0603B223K500CT - CAPACITOR, MLCC, X7R, 0.022UF, 50V, 0603; Manufacturer_Name: Walsin Technology Corporation; Geometry.Height: 0.87mm
C32 C35 = CMP-13271-003582-1: as C3 on sheet Sheet3
C38 = 0603X105K250CT: as C1 on sheet Sheet3
C54 C56 = VJ0603Y104KXACW1BC: Capacitor; Manufacturer_Name: Vishay
D2 = SS16-E3_61T: Diode; Manufacturer_Name: Vishay; Manufacturer_Part_Number: SS16-E3/61T
IC6 = TPS61165DBVT: Integrated Circuit; Manufacturer_Name: Texas Instruments
J2 = FH12-40S-0.5SH_55_: Connector; Manufacturer_Name: Hirose; Manufacturer_Part_Number: FH12-40S-0.5SH(55)
J15 = FH12-10S-0.5SH_55_: Connector; Manufacturer_Name: Hirose; Manufacturer_Part_Number: FH12-10S-0.5SH(55)
L2 = CMP-06042-000140-1: FIXED IND 10UH 1.49A 90 MOHM SMD; Tolerance: 20%
LED2 = KPTL-3216SURCK-01-VS: LED; Manufacturer_Name: Kingbright
P3 = CMP-1502-02331-3: Terminal Block, 5.08MM, Close Vertical Pcb Header, Thr Type, 4 Pins; Number of Contacts: 4; Voltage Rating: 300V; Current Rating: 10A; Gender: Male
R7 R17-R19 = CRCW06034K70JNEAC: Resistor; Manufacturer_Name: Vishay
R8 = RCA0603100KFKEA: AR03BTCX6R80; Manufacturer_Name: Vishay; Geometry.Height: 0.5mm
R16 = RCA0603100KFKEA: as R21 on sheet Sheet4

## Sheet Sheet6.SchDoc
size A4; SheetNumber: 6; SheetTotal: 6
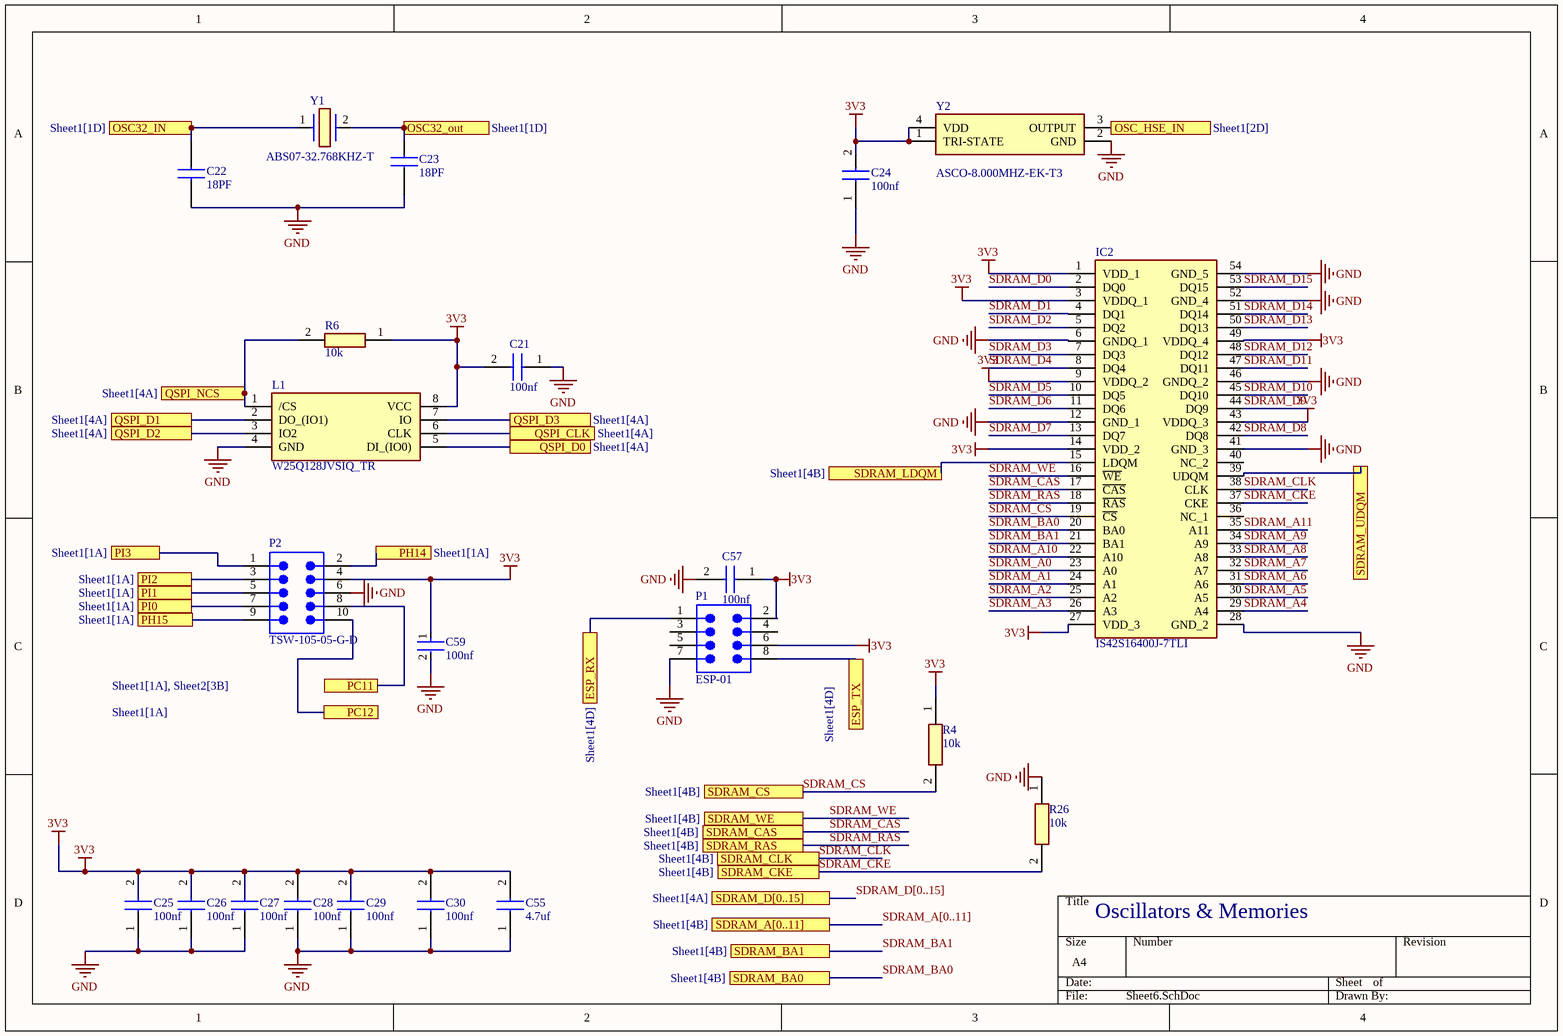
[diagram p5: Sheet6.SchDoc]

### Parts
C21  100nf  [CAPC1608X95N]
C22  18PF  [CAPC1608X87N]
C23  18PF  [CAPC1608X87N]
C24  100nf  [CAPC1608X95N]
C25  100nf  [CAPC1608X95N]
C26  100nf  [CAPC1608X95N]
C27  100nf  [CAPC1608X95N]
C28  100nf  [CAPC1608X95N]
C29  100nf  [CAPC1608X95N]
C30  100nf  [CAPC1608X95N]
C55  4.7uf  [CAPC1608X95N]
C57  100nf  [CAPC1608X95N]
C59  100nf  [FP-VJ0603X-MFG]
IC2  IS42S16400J-7TLI  [SOP80P1176X120-54N]
L1  W25Q128JVSIQ_TR  [SOIC127P780X195-8N]
P1  ESP-01  [SMTC-MTSW-104-12-X-D-006]
P2  TSW-105-05-G-D  [SMTC-TSW-105-05-X-D]
R4  10k  [RESC1608X55N]
R6  10k  [RESC1608X55N]
R26  10k  [RESC1608X55N]
Y1  ABS07-32.768KHZ-T  [ABS07]
Y2  ASCO-8.000MHZ-EK-T3  [ASCO16000MHZEKT]

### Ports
ESP_RX (see Sheet1[4D]), ESP_TX (see Sheet1[4D]), OSC32_IN (see Sheet1[1D]), OSC32_out (see Sheet1[1D]), OSC_HSE_IN (see Sheet1[2D]), PC11 (see Sheet1[1A], Sheet2[3B]), PC12 (see Sheet1[1A]), PH14 (see Sheet1[1A]), PH15 (see Sheet1[1A]), PI0 (see Sheet1[1A]), PI1 (see Sheet1[1A]), PI2 (see Sheet1[1A]), PI3 (see Sheet1[1A]), QSPI_CLK (see Sheet1[4A]), QSPI_D0 (see Sheet1[4A]), QSPI_D1 (see Sheet1[4A]), QSPI_D2 (see Sheet1[4A]), QSPI_D3 (see Sheet1[4A]), QSPI_NCS (see Sheet1[4A]), SDRAM_A[0..11] (see Sheet1[4B]), SDRAM_BA0 (see Sheet1[4B]), SDRAM_BA1 (see Sheet1[4B]), SDRAM_CAS (see Sheet1[4B]), SDRAM_CKE (see Sheet1[4B]), SDRAM_CLK (see Sheet1[4B]), SDRAM_CS (see Sheet1[4B]), SDRAM_D[0..15] (see Sheet1[4A]), SDRAM_LDQM (see Sheet1[4B]), SDRAM_RAS (see Sheet1[4B]), SDRAM_UDQM, SDRAM_WE (see Sheet1[4B])

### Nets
3V3: C21.2 C24.2 C25.2 C26.2 C27.2 C28.2 C29.2 C30.2 C55.2 C57.1 C59.1 IC2.1(VDD_1) IC2.3(VDDQ_1) IC2.9(VDDQ_2) IC2.14(VDD_2) IC2.27(VDD_3) IC2.43(VDDQ_3) IC2.49(VDDQ_4) L1.8(VCC) P1.2 P1.6 P2.4 R4.1 R6.1 Y2.1(TRI-STATE) Y2.4(VDD)
GND: C21.1 C22.1 C23.1 C24.1 C25.1 C26.1 C27.1 C28.1 C29.1 C30.1 C55.1 C57.2 C59.2 IC2.6(GNDQ_1) IC2.12(GND_1) IC2.28(GND_2) IC2.41(GND_3) IC2.46(GNDQ_2) IC2.52(GND_4) IC2.54(GND_5) L1.4(GND) P1.7 P2.6 R26.1 Y2.2(GND)
ESP_RX: P1.1 ; port ESP_RX
ESP_TX: P1.8 ; port ESP_TX
QSPI_CLK: L1.6(CLK) ; port QSPI_CLK
QSPI_D0: L1.5(DI_(IO0)) ; port QSPI_D0
QSPI_D1: L1.2(DO_(IO1)) ; port QSPI_D1
QSPI_D2: L1.3(IO2) ; port QSPI_D2
QSPI_D3: L1.7(IO) ; port QSPI_D3
QSPI_NCS: L1.1(/CS) R6.2 ; port QSPI_NCS
SDRAM_A0: IC2.23(A0)
SDRAM_A1: IC2.24(A1)
SDRAM_A2: IC2.25(A2)
SDRAM_A3: IC2.26(A3)
SDRAM_A4: IC2.29(A4)
SDRAM_A5: IC2.30(A5)
SDRAM_A6: IC2.31(A6)
SDRAM_A7: IC2.32(A7)
SDRAM_A8: IC2.33(A8)
SDRAM_A9: IC2.34(A9)
SDRAM_A10: IC2.22(A10)
SDRAM_A11: IC2.35(A11)
SDRAM_BA0: IC2.20(BA0) ; port SDRAM_BA0
SDRAM_BA1: IC2.21(BA1) ; port SDRAM_BA1
SDRAM_CAS: IC2.17(~{CAS}) ; port SDRAM_CAS
SDRAM_CKE: IC2.37(CKE) R26.2 ; port SDRAM_CKE
SDRAM_CLK: IC2.38(CLK) ; port SDRAM_CLK
SDRAM_CS: IC2.19(~{CS}) R4.2 ; port SDRAM_CS
SDRAM_D0: IC2.2(DQ0)
SDRAM_D1: IC2.4(DQ1)
SDRAM_D2: IC2.5(DQ2)
SDRAM_D3: IC2.7(DQ3)
SDRAM_D4: IC2.8(DQ4)
SDRAM_D5: IC2.10(DQ5)
SDRAM_D6: IC2.11(DQ6)
SDRAM_D7: IC2.13(DQ7)
SDRAM_D8: IC2.42(DQ8)
SDRAM_D9: IC2.44(DQ9)
SDRAM_D10: IC2.45(DQ10)
SDRAM_D11: IC2.47(DQ11)
SDRAM_D12: IC2.48(DQ12)
SDRAM_D13: IC2.50(DQ13)
SDRAM_D14: IC2.51(DQ14)
SDRAM_D15: IC2.53(DQ15)
SDRAM_LDQM: IC2.15(LDQM) ; port SDRAM_LDQM
SDRAM_RAS: IC2.18(~{RAS}) ; port SDRAM_RAS
SDRAM_UDQM: IC2.39(UDQM) ; port SDRAM_UDQM
SDRAM_WE: IC2.16(~{WE}) ; port SDRAM_WE
NetC22_2: C22.2 Y1.1 ; port OSC32_IN
NetC23_2: C23.2 Y1.2 ; port OSC32_out
NetIC1_32: Y2.3(OUTPUT) ; port OSC_HSE_IN
NetIC1_151: P2.9 ; port PH15
NetIC1_152: P2.2 ; port PH14
NetIC1_154: P2.7 ; port PI0
NetIC1_155: P2.5 ; port PI1
NetIC1_156: P2.3 ; port PI2
NetIC1_157: P2.1 ; port PI3
NetIC1_162: P2.8 ; port PC11
NetIC1_163: P2.10 ; port PC12

Not connected (* = marked no-connect by the designer): IC2 36(NC_1) 40(NC_2); P1 3 4 5

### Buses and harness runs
bus SDRAM_A[0..11] = port SDRAM_A[0..11]
bus SDRAM_D[0..15] = port SDRAM_D[0..15]

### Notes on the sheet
- Oscillators & Memories

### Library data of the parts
C21 C24-C30 C55 C57 = VJ0603Y104KXACW1BC: Capacitor; Manufacturer_Name: Vishay
C22 C23 = C0603C180J5GAC: Multilayer Ceramic Capacitors MLCC - SMD/SMT 50volts 18pF 5% C0G; Manufacturer_Name: KEMET; Geometry.Height: 0.87mm
C59 = CMP-02417-000051-1: CAP CER 0.1UF 50V X7R 0603; Tolerance: 10%; Dielectric Material: Tantalum
IC2 = IS42S16400J-7TLI: Integrated Circuit; Manufacturer_Name: Integrated Silicon Solution Inc.
L1 = W25Q128JVSIQ_TR: Inductor; Manufacturer_Name: Winbond; Manufacturer_Part_Number: W25Q128JVSIQ TR
P1 = CMP-1024-00110-1: Modified .025" SQ Post Header, Through-hole, Vertical, -55 to 105 degC, 2.54 mm Pitch, 8-Pin, Male, RoHS; PartNumber: MTSW-104-12-T-D-006; Manufacturer: Samtec; Pitch: 2.54 mm
P2 = CMP-1024-00362-1: 0.025" SQ Post Header, Through-hole, Vertical, -55 to 125 degC, 2.54 mm Pitch, 10-Pin, Male, RoHS; Manufacturer: Samtec; Pitch: 2.54 mm
R4 R6 R26 = RC0603FR-071KL: Resistor; Manufacturer_Name: YAGEO
Y1 = ABS07-32.768KHZ-T: Crystal or Oscillator; Manufacturer_Name: ABRACON
Y2 = ASCO-8.000MHZ-EK-T3: Crystal or Oscillator; Manufacturer_Name: ABRACON

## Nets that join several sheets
3V3: Sheet1 (19 pins), Sheet2 (12 pins), Sheet3 (19 pins), Sheet4 (19 pins), Sheet5 (7 pins), Sheet6 (26 pins)
+5: Sheet2 (9 pins), Sheet4 (6 pins), Sheet5 (C32.1 C54.2 IC6.1 L2.1)
GND: Sheet1 (16 pins), Sheet2 (27 pins), Sheet3 (24 pins), Sheet4 (20 pins), Sheet5 (22 pins), Sheet6 (25 pins)
VDDA: Sheet1 (IC1.42), Sheet3 (C5.1 C8.2 Ferrite_Chip_Bead.2 R5.2)
VREF+: Sheet1 (IC1.41), Sheet3 (C1.2 C2.2 R5.1)
ESP_RX: Sheet1 (IC1.143), Sheet6 (P1.1)
ESP_TX: Sheet1 (IC1.144), Sheet6 (P1.8)
LCD_B0: Sheet1 (IC1.3), Sheet5 (J2.21)
LCD_B1: Sheet1 (IC1.181), Sheet5 (J2.22)
LCD_B2: Sheet1 (IC1.172), Sheet5 (J2.23)
LCD_B3: Sheet1 (IC1.180), Sheet5 (J2.24)
LCD_B4: Sheet1 (IC1.205), Sheet5 (J2.25)
LCD_B5: Sheet1 (IC1.50), Sheet5 (J2.26)
LCD_B6: Sheet1 (IC1.188), Sheet5 (J2.27)
LCD_B7: Sheet1 (IC1.189), Sheet5 (J2.28)
LCD_BL_CTRL: Sheet1 (IC1.140), Sheet5 (P3.2)
LCD_DCLK: Sheet1 (IC1.21), Sheet5 (J2.30)
LCD_DE: Sheet1 (IC1.190), Sheet5 (J2.34)
LCD_DISP: Sheet1 (IC1.183), Sheet5 (J2.31 R7.2)
LCD_G0: Sheet1 (IC1.4), Sheet5 (J2.13)
LCD_G1: Sheet1 (IC1.5), Sheet5 (J2.14)
LCD_G2: Sheet1 (IC1.55), Sheet5 (J2.15)
LCD_G3: Sheet1 (IC1.179), Sheet5 (J2.16)
LCD_G4: Sheet1 (IC1.90), Sheet5 (J2.17)
LCD_G5: Sheet1 (IC1.91), Sheet5 (J2.18)
LCD_G6: Sheet1 (IC1.139), Sheet5 (J2.19)
LCD_G7: Sheet1 (IC1.167), Sheet5 (J2.20)
LCD_HSYNC: Sheet1 (IC1.12), Sheet5 (J2.32)
LCD_INT: Sheet1 (IC1.58), Sheet5 (J2.38 J15.2)
LCD_R0: Sheet1 (IC1.182), Sheet5 (J2.5)
LCD_R1: Sheet1 (IC1.65), Sheet5 (J2.6)
LCD_R2: Sheet1 (IC1.66), Sheet5 (J2.7)
LCD_R3: Sheet1 (IC1.61), Sheet5 (J2.8)
LCD_R4: Sheet1 (IC1.145), Sheet5 (J2.9)
LCD_R5: Sheet1 (IC1.35), Sheet5 (J2.10)
LCD_R6: Sheet1 (IC1.62), Sheet5 (J2.11)
LCD_R7: Sheet1 (IC1.133), Sheet5 (J2.12)
LCD_RST: Sheet1 (IC1.57), Sheet5 (J2.37 J15.4)
LCD_SCL: Sheet1 (IC1.198), Sheet5 (J2.39 J15.8 R18.1)
LCD_SDA: Sheet1 (IC1.199), Sheet5 (J2.40 J15.6 R17.1)
LCD_VSYNC: Sheet1 (IC1.11), Sheet5 (J2.33)
NetC6_1: Sheet1 (IC1.148), Sheet3 (C6.1)
NetC7_1: Sheet1 (IC1.92), Sheet3 (C7.1)
NetC22_2: Sheet1 (IC1.9), Sheet6 (C22.2 Y1.1)
NetC23_2: Sheet1 (IC1.10), Sheet6 (C23.2 Y1.2)
NetC41_2: Sheet1 (IC1.44), Sheet4 (5 pins)
NetIC1_32: Sheet1 (IC1.32), Sheet6 (Y2.3)
NetIC1_46: Sheet1 (IC1.46), Sheet4 (IC8.1 R13.2 R15.1 R25.1)
NetIC1_97: Sheet1 (IC1.97), Sheet4 (IC4.4 R12.2)
NetIC1_98: Sheet1 (IC1.98), Sheet4 (IC4.3 R10.1)
NetIC1_101: Sheet1 (IC1.101), Sheet4 (IC3.9 R11.2)
NetIC1_102: Sheet1 (IC1.102), Sheet4 (IC3.10 R9.1)
NetIC1_127: Sheet1 (IC1.127), Sheet4 (R20.1)
NetIC1_151: Sheet1 (IC1.151 IC1.153), Sheet6 (P2.9)
NetIC1_152: Sheet1 (IC1.152), Sheet6 (P2.2)
NetIC1_154: Sheet1 (IC1.154), Sheet6 (P2.7)
NetIC1_155: Sheet1 (IC1.155), Sheet6 (P2.5)
NetIC1_156: Sheet1 (IC1.156), Sheet6 (P2.3)
NetIC1_157: Sheet1 (IC1.157), Sheet6 (P2.1)
NetIC1_161: Sheet1 (IC1.161), Sheet2 (U1.5)
NetIC1_162: Sheet1 (IC1.162), Sheet2 (U1.6), Sheet6 (P2.8)
NetIC1_163: Sheet1 (IC1.163), Sheet6 (P2.10)
NRST: Sheet1 (IC1.34 R3.1), Sheet2 (J3.12)
QSPI_CLK: Sheet1 (IC1.63), Sheet6 (L1.6)
QSPI_D0: Sheet1 (IC1.29), Sheet6 (L1.5)
QSPI_D1: Sheet1 (IC1.30), Sheet6 (L1.2)
QSPI_D2: Sheet1 (IC1.28), Sheet6 (L1.3)
QSPI_D3: Sheet1 (IC1.27), Sheet6 (L1.7)
QSPI_NCS: Sheet1 (IC1.195), Sheet6 (L1.1 R6.2)
SDRAM_A0: Sheet1 (IC1.16), Sheet6 (IC2.23)
SDRAM_A1: Sheet1 (IC1.17), Sheet6 (IC2.24)
SDRAM_A2: Sheet1 (IC1.18), Sheet6 (IC2.25)
SDRAM_A3: Sheet1 (IC1.22), Sheet6 (IC2.26)
SDRAM_A4: Sheet1 (IC1.23), Sheet6 (IC2.29)
SDRAM_A5: Sheet1 (IC1.24), Sheet6 (IC2.30)
SDRAM_A6: Sheet1 (IC1.71), Sheet6 (IC2.31)
SDRAM_A7: Sheet1 (IC1.74), Sheet6 (IC2.32)
SDRAM_A8: Sheet1 (IC1.75), Sheet6 (IC2.33)
SDRAM_A9: Sheet1 (IC1.76), Sheet6 (IC2.34)
SDRAM_A10: Sheet1 (IC1.77), Sheet6 (IC2.22)
SDRAM_A11: Sheet1 (IC1.78), Sheet6 (IC2.35)
SDRAM_BA0: Sheet1 (IC1.131), Sheet6 (IC2.20)
SDRAM_BA1: Sheet1 (IC1.132), Sheet6 (IC2.21)
SDRAM_CAS: Sheet1 (IC1.191), Sheet6 (IC2.17)
SDRAM_CKE: Sheet1 (IC1.38), Sheet6 (IC2.37 R26.2)
SDRAM_CLK: Sheet1 (IC1.135), Sheet6 (IC2.38)
SDRAM_CS: Sheet1 (IC1.37), Sheet6 (IC2.19 R4.2)
SDRAM_D0: Sheet1 (IC1.116), Sheet6 (IC2.2)
SDRAM_D1: Sheet1 (IC1.117), Sheet6 (IC2.4)
SDRAM_D2: Sheet1 (IC1.164), Sheet6 (IC2.5)
SDRAM_D3: Sheet1 (IC1.165), Sheet6 (IC2.7)
SDRAM_D4: Sheet1 (IC1.79), Sheet6 (IC2.8)
SDRAM_D5: Sheet1 (IC1.80), Sheet6 (IC2.10)
SDRAM_D6: Sheet1 (IC1.81), Sheet6 (IC2.11)
SDRAM_D7: Sheet1 (IC1.84), Sheet6 (IC2.13)
SDRAM_D8: Sheet1 (IC1.85), Sheet6 (IC2.42)
SDRAM_D9: Sheet1 (IC1.86), Sheet6 (IC2.44)
SDRAM_D10: Sheet1 (IC1.87), Sheet6 (IC2.45)
SDRAM_D11: Sheet1 (IC1.88), Sheet6 (IC2.47)
SDRAM_D12: Sheet1 (IC1.89), Sheet6 (IC2.48)
SDRAM_D13: Sheet1 (IC1.108), Sheet6 (IC2.50)
SDRAM_D14: Sheet1 (IC1.109), Sheet6 (IC2.51)
SDRAM_D15: Sheet1 (IC1.110), Sheet6 (IC2.53)
SDRAM_LDQM: Sheet1 (IC1.200), Sheet6 (IC2.15)
SDRAM_RAS: Sheet1 (IC1.70), Sheet6 (IC2.18)
SDRAM_UDQM: Sheet1 (IC1.201), Sheet6 (IC2.39)
SDRAM_WE: Sheet1 (IC1.49), Sheet6 (IC2.16)
SWCLK: Sheet1 (IC1.159), Sheet2 (J3.6)
SWDIO: Sheet1 (IC1.147), Sheet2 (J3.4)
SWO: Sheet1 (IC1.192), Sheet2 (J3.8)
